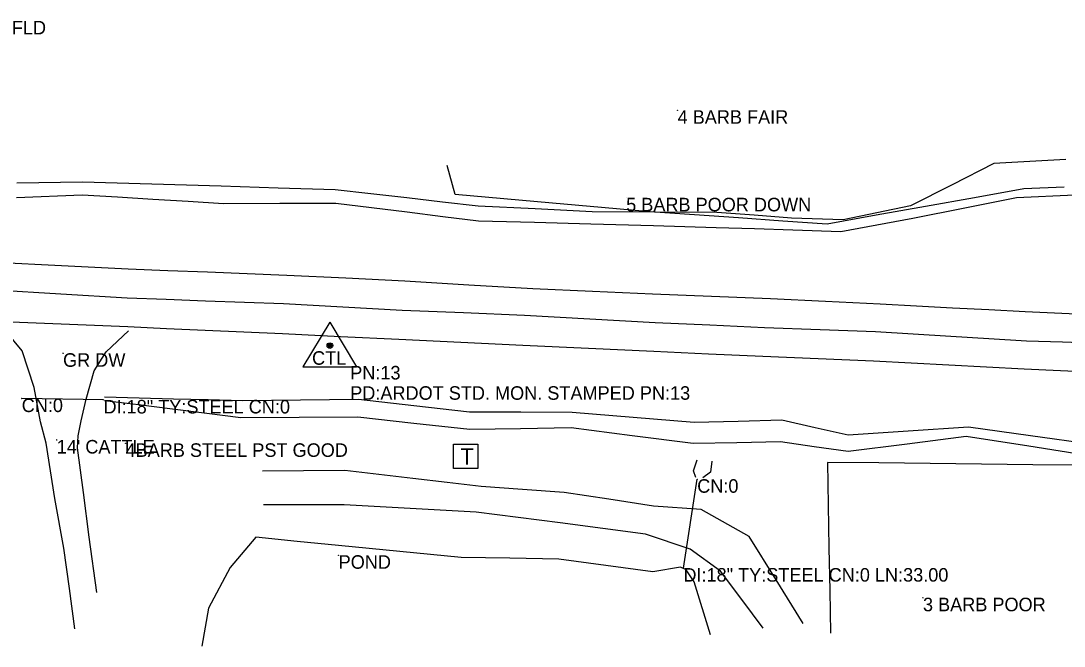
# Model space of a CAD drawing. Extents: x 1138803 to 1169983, y 1655906 to 1658226.
# Drawn here: x 1164210.1 to 1164595.4, y 1656647.5 to 1656878.4 of the extents above; entities that cross this region are included whole.
import ezdxf

# ---------------------------------------------------------------- set-up
doc = ezdxf.new("R2010")
doc.units = 0
for name, color, linetype in [('S_DITCHLINE', 7, 'Continuous'), ('S_DRG_PT_SYM', 7, 'Continuous'), ('S_DRIVEWAY', 7, 'Continuous'), ('S_EDGE_PAVEMENT', 7, 'Continuous'), ('S_GATE_ANNOT', 7, 'Continuous'), ('S_LEVEE', 7, 'Continuous'), ('S_MSC_PT_SYM', 7, 'Continuous'), ('S_PAVEMENT_CROWN', 7, 'Continuous'), ('S_PRIMARY_CTL', 7, 'Continuous'), ('S_PRIMARY_CTL_ANNOT', 7, 'Continuous'), ('S_SIDE_DRAIN', 7, 'Continuous'), ('S_SIDE_DRAIN_ANNOT', 7, 'Continuous'), ('S_STREAM', 7, 'Continuous'), ('S_SURVEY_TEXT_ANNOT', 7, 'Continuous'), ('S_TELEPHONE_UTILITIES', 7, 'Continuous'), ('S_TREE', 7, 'Continuous')]:
    doc.layers.add(name, color=color, linetype=linetype)

msp = doc.modelspace()

# ---------------------------------------------------------------- linework, layer by layer
at = {"layer": 'S_DITCHLINE'}
for points in [[(1164596.01, 1656827.16), (1164582.75, 1656826.46), (1164569.49, 1656825.76), (1164554.1, 1656817.91), (1164538.7, 1656810.07), (1164526.24, 1656807.51), (1164513.78, 1656804.94), (1164494.73, 1656805.5), (1164480.9, 1656806.6), (1164467.08, 1656807.7), (1164444.08, 1656807.81), (1164421.08, 1656807.91), (1164400.05, 1656808.95), (1164379.02, 1656809.99), (1164365.79, 1656811.5), (1164352.56, 1656813), (1164339.33, 1656814.5), (1164326.09, 1656816.01), (1164305.08, 1656816.66), (1164284.07, 1656817.32), (1164271.25, 1656817.7), (1164258.44, 1656818.09), (1164245.63, 1656818.47), (1164232.81, 1656818.85), (1164208.55, 1656818.49)], [(1164599.31, 1656814.04), (1164577.81, 1656813.08), (1164558.67, 1656809.26), (1164539.53, 1656805.43), (1164526.23, 1656802.98), (1164512.93, 1656800.54), (1164495.23, 1656801.16), (1164481.08, 1656801.57), (1164466.93, 1656801.98), (1164443.73, 1656802.68), (1164420.54, 1656803.38), (1164399.79, 1656803.91), (1164379.04, 1656804.44), (1164365.88, 1656806.09), (1164352.73, 1656807.73), (1164339.57, 1656809.38), (1164326.42, 1656811.03), (1164305.65, 1656810.94), (1164284.87, 1656810.85), (1164271.82, 1656811.65), (1164258.78, 1656812.45), (1164245.73, 1656813.25), (1164232.68, 1656814.06), (1164208.48, 1656813.07)], [(1164605.53, 1656717.64), (1164582.38, 1656721.3), (1164559.24, 1656724.96), (1164537.42, 1656722.15), (1164515.6, 1656719.34), (1164503.11, 1656721.14), (1164490.62, 1656722.93), (1164474.48, 1656722.64), (1164458.34, 1656722.35), (1164435.85, 1656725.22), (1164413.36, 1656728.09), (1164394.64, 1656727.81), (1164375.92, 1656727.53), (1164355.2, 1656729.79), (1164334.48, 1656732.06), (1164312.87, 1656731.94), (1164291.26, 1656731.82), (1164278.69, 1656733.4), (1164266.12, 1656734.99), (1164253.55, 1656736.58), (1164240.98, 1656738.16)], [(1164605.97, 1656721.98), (1164583.02, 1656725.15), (1164560.07, 1656728.33), (1164537.83, 1656726.88), (1164515.58, 1656725.42), (1164503.38, 1656728.19), (1164491.18, 1656730.95), (1164474.96, 1656730.5), (1164458.74, 1656730.04), (1164436.22, 1656731.94), (1164413.7, 1656733.83), (1164394.72, 1656733.9), (1164375.74, 1656733.97), (1164355.25, 1656736.29), (1164334.76, 1656738.61), (1164313.35, 1656738.35), (1164291.94, 1656738.09), (1164279.21, 1656738.42), (1164266.47, 1656738.76), (1164253.73, 1656739.09), (1164241, 1656739.42)], [(1164459.32, 1656709.79), (1164458.53, 1656712.3), (1164459.83, 1656716.35)], [(1164465.29, 1656715.78), (1164464.8, 1656711.73), (1164461.98, 1656709.66)]]:
    msp.add_lwpolyline(points, dxfattribs=at)
at = {"layer": 'S_DRG_PT_SYM'}
for points in [[(1164210.37, 1656738.95), (1164210.37, 1656739), (1164210.37, 1656738.95), (1164210.32, 1656738.95), (1164210.37, 1656738.95), (1164210.37, 1656738.9), (1164210.37, 1656738.95), (1164210.42, 1656738.95)], [(1164240.57, 1656738.44), (1164240.57, 1656738.49), (1164240.57, 1656738.44), (1164240.52, 1656738.44), (1164240.57, 1656738.44), (1164240.57, 1656738.39), (1164240.57, 1656738.44), (1164240.62, 1656738.44)], [(1164459.87, 1656709.16), (1164459.87, 1656709.21), (1164459.87, 1656709.16), (1164459.82, 1656709.16), (1164459.87, 1656709.16), (1164459.87, 1656709.11), (1164459.87, 1656709.16), (1164459.92, 1656709.16)], [(1164454.77, 1656676.34), (1164454.77, 1656676.39), (1164454.77, 1656676.34), (1164454.72, 1656676.34), (1164454.77, 1656676.34), (1164454.77, 1656676.29), (1164454.77, 1656676.34), (1164454.82, 1656676.34)]]:
    msp.add_lwpolyline(points, dxfattribs=at)
at = {"layer": 'S_DRIVEWAY'}
for points in [[(1164230.04, 1656653.94), (1164227.96, 1656668.83), (1164225.87, 1656683.72), (1164222.6, 1656702.08), (1164219.44, 1656722.52), (1164217.3, 1656730.32), (1164214.92, 1656743.01), (1164210.53, 1656756.51), (1164202.18, 1656766.52)], [(1164238.12, 1656667.34), (1164235.32, 1656687.72), (1164233.18, 1656704.25), (1164231.03, 1656720.78), (1164231.22, 1656725.15), (1164232.33, 1656730.73), (1164234.18, 1656738.69), (1164237.1, 1656749.21), (1164241.52, 1656756.21), (1164249.84, 1656763.93)]]:
    msp.add_lwpolyline(points, dxfattribs=at)
at = {"layer": 'S_EDGE_PAVEMENT'}
for points in [[(1164608.03, 1656769.75), (1164594.5, 1656770.34), (1164580.97, 1656770.94), (1164567.58, 1656771.65), (1164554.2, 1656772.37), (1164540.81, 1656773.09), (1164527.43, 1656773.81), (1164507.2, 1656774.82), (1164486.98, 1656775.82), (1164465.14, 1656776.65), (1164443.31, 1656777.47), (1164421.22, 1656778.47), (1164399.13, 1656779.47), (1164375.48, 1656780.87), (1164351.83, 1656782.27), (1164330.04, 1656783.35), (1164308.25, 1656784.43), (1164293.6, 1656785), (1164278.96, 1656785.57), (1164264.32, 1656786.14), (1164249.68, 1656786.71), (1164225.06, 1656787.93), (1164200.44, 1656789.14)], [(1164607.41, 1656748.54), (1164594, 1656749.15), (1164580.6, 1656749.76), (1164566.69, 1656750.51), (1164552.77, 1656751.25), (1164538.86, 1656752), (1164524.95, 1656752.74), (1164504.53, 1656753.59), (1164484.12, 1656754.44), (1164464.01, 1656755.37), (1164443.91, 1656756.29), (1164419.68, 1656757.41), (1164395.46, 1656758.54), (1164372.54, 1656759.64), (1164349.63, 1656760.74), (1164328.16, 1656761.76), (1164306.68, 1656762.79), (1164292.41, 1656763.43), (1164278.15, 1656764.08), (1164263.88, 1656764.73), (1164249.61, 1656765.38), (1164224.92, 1656766.41), (1164200.22, 1656767.45)]]:
    msp.add_lwpolyline(points, dxfattribs=at)
at = {"layer": 'S_LEVEE'}
for points in [[(1164499.01, 1656655.94), (1164489.01, 1656671.95), (1164479.01, 1656687.97), (1164461.37, 1656697.95), (1164443.69, 1656699.23), (1164427.2, 1656701.75), (1164410.71, 1656704.28), (1164395.38, 1656705.35), (1164380.06, 1656706.41), (1164367.47, 1656707.91), (1164354.88, 1656709.42), (1164342.29, 1656710.92), (1164329.69, 1656712.43), (1164314.48, 1656712.26), (1164299.27, 1656712.09)], [(1164484.24, 1656654.2), (1164476.39, 1656664.7), (1164468.53, 1656675.21), (1164457.31, 1656683.37), (1164440.82, 1656688.92), (1164425.01, 1656690.97), (1164409.2, 1656693.02), (1164393.7, 1656695.03), (1164378.19, 1656697.04), (1164353.82, 1656698.39), (1164329.44, 1656699.75), (1164314.54, 1656699.73), (1164299.63, 1656699.72)]]:
    msp.add_lwpolyline(points, dxfattribs=at)
at = {"layer": 'S_MSC_PT_SYM'}
for points in [[(1164452.63, 1656845.41), (1164452.63, 1656845.46), (1164452.63, 1656845.41), (1164452.58, 1656845.41), (1164452.63, 1656845.41), (1164452.63, 1656845.36), (1164452.63, 1656845.41), (1164452.68, 1656845.41)], [(1164433.63, 1656813.07), (1164433.63, 1656813.12), (1164433.63, 1656813.07), (1164433.58, 1656813.07), (1164433.63, 1656813.07), (1164433.63, 1656813.02), (1164433.63, 1656813.07), (1164433.68, 1656813.07)], [(1164225.65, 1656755.67), (1164225.65, 1656755.72), (1164225.65, 1656755.67), (1164225.6, 1656755.67), (1164225.65, 1656755.67), (1164225.65, 1656755.62), (1164225.65, 1656755.67), (1164225.7, 1656755.67)], [(1164223.29, 1656723.65), (1164223.29, 1656723.7), (1164223.29, 1656723.65), (1164223.24, 1656723.65), (1164223.29, 1656723.65), (1164223.29, 1656723.6), (1164223.29, 1656723.65), (1164223.34, 1656723.65)], [(1164248.72, 1656722.41), (1164248.72, 1656722.46), (1164248.72, 1656722.41), (1164248.67, 1656722.41), (1164248.72, 1656722.41), (1164248.72, 1656722.36), (1164248.72, 1656722.41), (1164248.77, 1656722.41)], [(1164327.43, 1656681.09), (1164327.43, 1656681.14), (1164327.43, 1656681.09), (1164327.38, 1656681.09), (1164327.43, 1656681.09), (1164327.43, 1656681.04), (1164327.43, 1656681.09), (1164327.48, 1656681.09)], [(1164543.26, 1656665.4), (1164543.26, 1656665.45), (1164543.26, 1656665.4), (1164543.21, 1656665.4), (1164543.26, 1656665.4), (1164543.26, 1656665.35), (1164543.26, 1656665.4), (1164543.31, 1656665.4)]]:
    msp.add_lwpolyline(points, dxfattribs=at)
at = {"layer": 'S_PAVEMENT_CROWN'}
msp.add_lwpolyline([(1164608.14, 1656759.32), (1164594.8, 1656759.74), (1164581.46, 1656760.16), (1164567.53, 1656761.02), (1164553.61, 1656761.88), (1164539.68, 1656762.74), (1164525.76, 1656763.61), (1164505.27, 1656764.34), (1164484.78, 1656765.07), (1164464.56, 1656766.01), (1164444.35, 1656766.95), (1164420.25, 1656768.3), (1164396.14, 1656769.65), (1164373.52, 1656770.56), (1164350.91, 1656771.46), (1164328.99, 1656772.66), (1164307.06, 1656773.86), (1164292.63, 1656774.41), (1164278.2, 1656774.96), (1164263.76, 1656775.51), (1164249.33, 1656776.06), (1164224.86, 1656777.51), (1164200.4, 1656778.96)], dxfattribs=at)
at = {"layer": 'S_PRIMARY_CTL'}
for p, q in [((1164324.2, 1656767.2), (1164314.17, 1656750.68)), ((1164324.2, 1656767.2), (1164334.03, 1656750.68)), ((1164314.17, 1656750.68), (1164334.03, 1656750.68))]:
    msp.add_line(p, q, dxfattribs=at)
for radius in [1.04, 0.609, 0.344]:
    msp.add_circle((1164324.2, 1656758.49), radius, dxfattribs=at)
at = {"layer": 'S_SIDE_DRAIN'}
for p, q in [((1164240.57, 1656738.44), (1164210.37, 1656738.95)), ((1164454.77, 1656676.34), (1164459.87, 1656709.16))]:
    msp.add_line(p, q, dxfattribs=at)
at = {"layer": 'S_STREAM'}
msp.add_lwpolyline([(1164464.82, 1656651.7), (1164458.78, 1656671.31), (1164455.74, 1656675.65), (1164453.73, 1656676.64), (1164443.46, 1656674.95), (1164426.08, 1656677.3), (1164408.71, 1656679.64), (1164390.72, 1656679.97), (1164372.73, 1656680.3), (1164350.03, 1656682.48), (1164327.34, 1656684.65), (1164312.1, 1656686.21), (1164296.85, 1656687.77), (1164287.33, 1656676.61), (1164279.33, 1656661.57), (1164276.89, 1656647.52)], dxfattribs=at)
at = {"layer": 'S_TELEPHONE_UTILITIES'}
msp.add_lwpolyline([(1164369.86, 1656713.08), (1164369.86, 1656722.08), (1164378.86, 1656722.08), (1164378.86, 1656713.08)], close=True, dxfattribs=at)
at = {"layer": 'S_TREE'}
for points in [[(1164595.41, 1656816.95), (1164580.51, 1656816.38), (1164562.34, 1656813.12), (1164544.17, 1656809.86), (1164526, 1656806.61), (1164507.83, 1656803.35), (1164491.5, 1656804.5), (1164475.17, 1656805.65), (1164458.84, 1656806.8), (1164442.51, 1656807.95), (1164424.49, 1656809.55), (1164406.46, 1656811.15), (1164388.44, 1656812.74), (1164370.42, 1656814.34), (1164367.56, 1656825.04)], [(1164602.73, 1656714.3), (1164583.79, 1656714.52), (1164564.85, 1656714.73), (1164545.91, 1656714.95), (1164526.97, 1656715.16), (1164508.03, 1656715.38), (1164508.29, 1656699.6), (1164508.54, 1656683.81), (1164508.8, 1656668.03), (1164509.05, 1656652.25)]]:
    msp.add_lwpolyline(points, dxfattribs=at)

# ---------------------------------------------------------------- texts
at = {"layer": 'S_GATE_ANNOT'}
msp.add_text("14' CATTLE", height=5, dxfattribs=at).set_placement((1164223.29, 1656718.65))
at = {"layer": 'S_PRIMARY_CTL'}
msp.add_text('CTL', height=5, rotation=360, dxfattribs=at).set_placement((1164317.62, 1656751.42))
at = {"layer": 'S_PRIMARY_CTL_ANNOT'}
for s, p in [('PN:13', (1164331.7, 1656745.99)), ('PD:ARDOT STD. MON. STAMPED PN:13', (1164331.7, 1656738.49))]:
    msp.add_text(s, height=5, dxfattribs=at).set_placement(p)
at = {"layer": 'S_SIDE_DRAIN_ANNOT'}
for s, p in [('CN:0', (1164210.37, 1656733.95)), ('DI:18" TY:STEEL CN:0', (1164240.57, 1656733.44)), ('CN:0', (1164459.87, 1656704.16)), ('DI:18" TY:STEEL CN:0 LN:33.00', (1164454.77, 1656671.34))]:
    msp.add_text(s, height=5, dxfattribs=at).set_placement(p)
at = {"layer": 'S_SURVEY_TEXT_ANNOT'}
for s, p in [('HAY FLD', (1164191.12, 1656873.41)), ('4 BARB FAIR', (1164452.63, 1656840.41)), ('5 BARB POOR DOWN', (1164433.63, 1656808.07)), ('GR DW', (1164225.65, 1656750.67)), ('4BARB STEEL PST GOOD', (1164248.72, 1656717.41)), ('POND', (1164327.43, 1656676.09)), ('3 BARB POOR', (1164543.26, 1656660.4))]:
    msp.add_text(s, height=5, dxfattribs=at).set_placement(p)
at = {"layer": 'S_TELEPHONE_UTILITIES'}
msp.add_text('T', height=6, rotation=360, dxfattribs=at).set_placement((1164372.43, 1656714.58))

doc.saveas('drawing.dxf')
